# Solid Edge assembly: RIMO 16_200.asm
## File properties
Title: Zylinder
Author: ahadarics
Template: iso metric assembly.asm
Last saved by: ahadarics
Revision: 20
Application: Solid Edge
Username: ahadarics
Dokumentum tartalom típus: 1
Document Number: RIMO 16/200
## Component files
Profilrohr.par
Kolbenstange.par
Kit_1.par
Kit_2.par
Mutter_1.par
Mutter_2.par
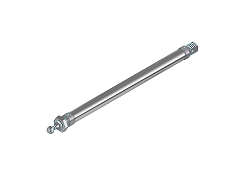
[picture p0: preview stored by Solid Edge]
